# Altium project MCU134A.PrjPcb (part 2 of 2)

## Sheet MCU134A_180pin_Edge_Connector.SchDoc
size 431 x 279 mm; SheetNumber: 11; SheetTotal: 13
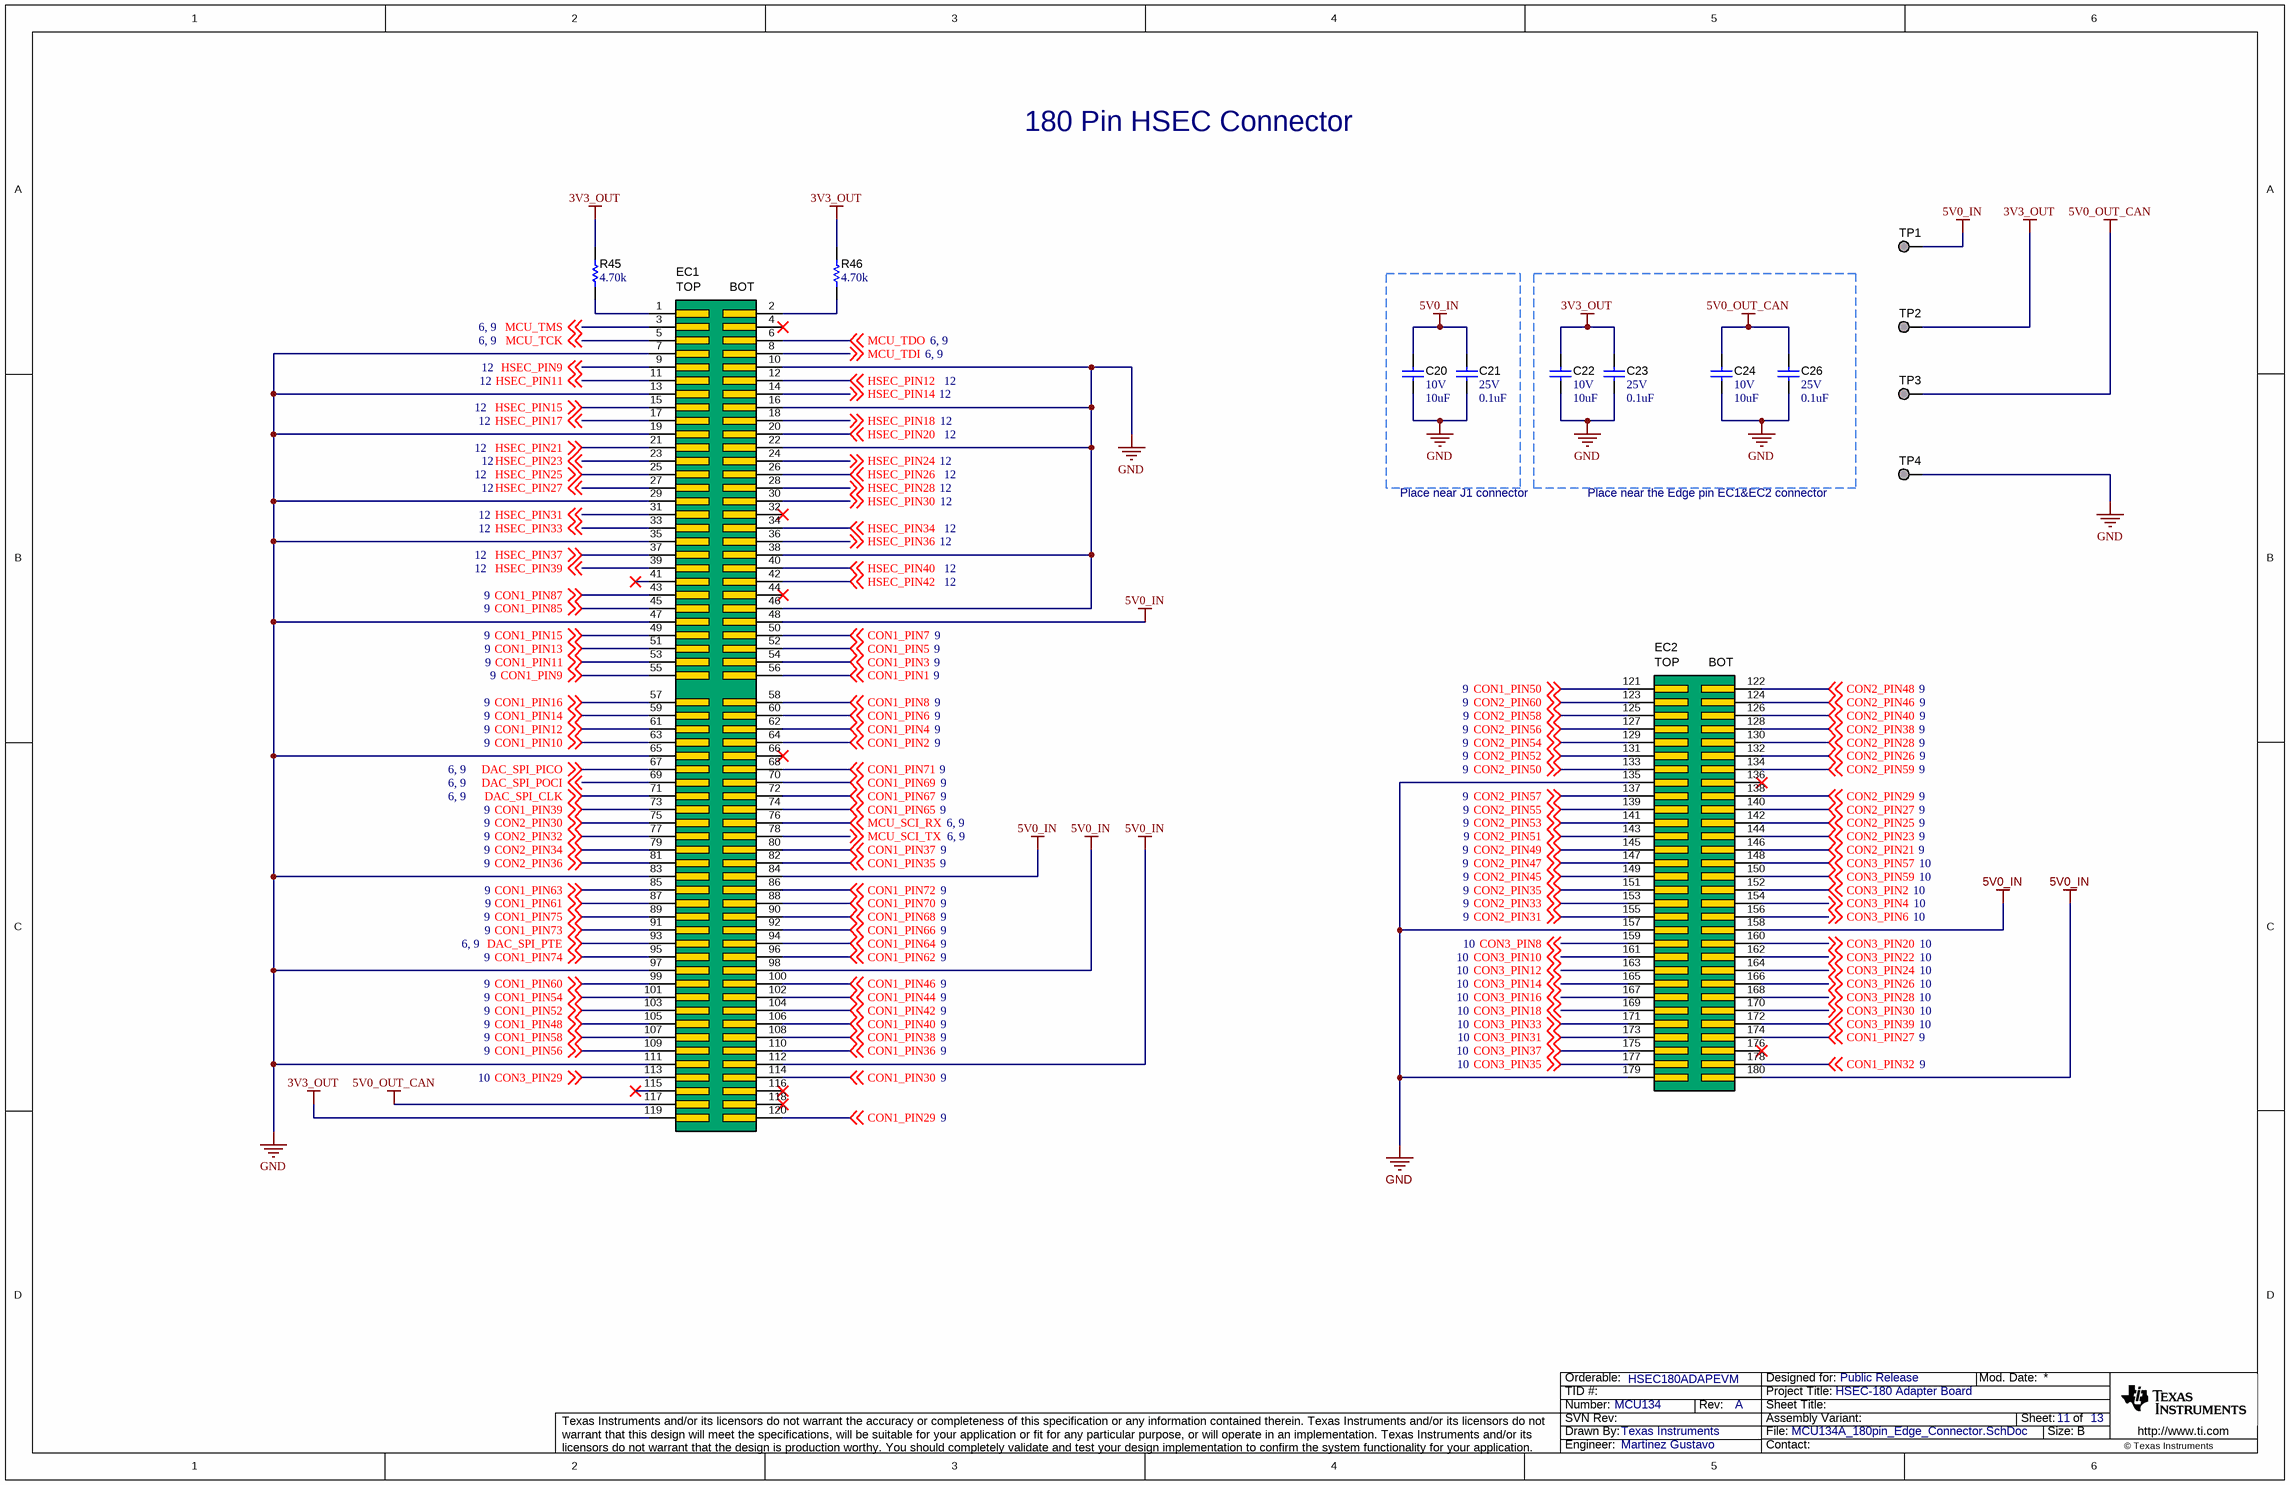
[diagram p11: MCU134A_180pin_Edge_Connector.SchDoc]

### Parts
C20  VDC_V: 10V  ValueDisplayed: 10uF  [0402]  (hidden comment: GRM155R61A106ME11D)
C21  VDC_V: 25V  ValueDisplayed: 0.1uF  [0402]  (hidden comment: GRM155R71E104KE14D)
C22  VDC_V: 10V  ValueDisplayed: 10uF  [0402]  (hidden comment: GRM155R61A106ME11D)
C23  VDC_V: 25V  ValueDisplayed: 0.1uF  [0402]  (hidden comment: GRM155R71E104KE14D)
C24  VDC_V: 10V  ValueDisplayed: 10uF  [0402]  (hidden comment: GRM155R61A106ME11D)
C26  VDC_V: 25V  ValueDisplayed: 0.1uF  [0402]  (hidden comment: GRM155R71E104KE14D)
EC1  controlCARD-120HSEC_Edge  [controlCARD-120HSEC_Edge]  (value not drawn)  (no BOM)
EC2  controlCARD-180HSEC-60pinAddon_Edge  [controlCARD-180HSEC-60pinAddon_Edge]  (value not drawn)  (no BOM)
R45  ValueDisplayed: 4.70k  [0402]  (hidden comment: CRG0402F4K7)
R46  ValueDisplayed: 4.70k  [0402]  (hidden comment: CRG0402F4K7)
TP1  CMP-0078143-4  [TESTPOINT]  (value not drawn)  (no BOM)
TP2  CMP-0078143-4  [TESTPOINT]  (value not drawn)  (no BOM)
TP3  CMP-0078143-4  [TESTPOINT]  (value not drawn)  (no BOM)
TP4  CMP-0078143-4  [TESTPOINT]  (value not drawn)  (no BOM)

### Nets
3V3_OUT: C22.1 C23.1 EC1.119 R45.2 R46.2 TP2.1
5V0_IN: C20.1 C21.1 EC1.48 EC1.84 EC1.98 EC1.112 EC2.158 EC2.180 TP1.1
5V0_OUT_CAN: C24.1 C26.1 EC1.117 TP3.1
GND: C20.2 C21.2 C22.2 C23.2 C24.2 C26.2 EC1.7 EC1.10 EC1.13 EC1.16 EC1.19 EC1.22 EC1.29 EC1.35 EC1.38 EC1.46 EC1.47 EC1.65 EC1.83 EC1.97 EC1.111 EC2.135 EC2.157 EC2.179 TP4.1
CON1_PIN1: EC1.56 ; off-sheet CON1_PIN1
CON1_PIN2: EC1.64 ; off-sheet CON1_PIN2
CON1_PIN3: EC1.54 ; off-sheet CON1_PIN3
CON1_PIN4: EC1.62 ; off-sheet CON1_PIN4
CON1_PIN5: EC1.52 ; off-sheet CON1_PIN5
CON1_PIN6: EC1.60 ; off-sheet CON1_PIN6
CON1_PIN7: EC1.50 ; off-sheet CON1_PIN7
CON1_PIN8: EC1.58 ; off-sheet CON1_PIN8
CON1_PIN9: EC1.55 ; off-sheet CON1_PIN9
CON1_PIN10: EC1.63 ; off-sheet CON1_PIN10
CON1_PIN11: EC1.53 ; off-sheet CON1_PIN11
CON1_PIN12: EC1.61 ; off-sheet CON1_PIN12
CON1_PIN13: EC1.51 ; off-sheet CON1_PIN13
CON1_PIN14: EC1.59 ; off-sheet CON1_PIN14
CON1_PIN15: EC1.49 ; off-sheet CON1_PIN15
CON1_PIN16: EC1.57 ; off-sheet CON1_PIN16
CON1_PIN27: EC2.174 ; off-sheet CON1_PIN27
CON1_PIN29: EC1.120 ; off-sheet CON1_PIN29
CON1_PIN30: EC1.114 ; off-sheet CON1_PIN30
CON1_PIN32: EC2.178 ; off-sheet CON1_PIN32
CON1_PIN35: EC1.82 ; off-sheet CON1_PIN35
CON1_PIN36: EC1.110 ; off-sheet CON1_PIN36
CON1_PIN37: EC1.80 ; off-sheet CON1_PIN37
CON1_PIN38: EC1.108 ; off-sheet CON1_PIN38
CON1_PIN39: EC1.73 ; off-sheet CON1_PIN39
CON1_PIN40: EC1.106 ; off-sheet CON1_PIN40
CON1_PIN42: EC1.104 ; off-sheet CON1_PIN42
CON1_PIN44: EC1.102 ; off-sheet CON1_PIN44
CON1_PIN46: EC1.100 ; off-sheet CON1_PIN46
CON1_PIN48: EC1.105 ; off-sheet CON1_PIN48
CON1_PIN50: EC2.121 ; off-sheet CON1_PIN50
CON1_PIN52: EC1.103 ; off-sheet CON1_PIN52
CON1_PIN54: EC1.101 ; off-sheet CON1_PIN54
CON1_PIN56: EC1.109 ; off-sheet CON1_PIN56
CON1_PIN58: EC1.107 ; off-sheet CON1_PIN58
CON1_PIN60: EC1.99 ; off-sheet CON1_PIN60
CON1_PIN61: EC1.87 ; off-sheet CON1_PIN61
CON1_PIN62: EC1.96 ; off-sheet CON1_PIN62
CON1_PIN63: EC1.85 ; off-sheet CON1_PIN63
CON1_PIN64: EC1.94 ; off-sheet CON1_PIN64
CON1_PIN65: EC1.74 ; off-sheet CON1_PIN65
CON1_PIN66: EC1.92 ; off-sheet CON1_PIN66
CON1_PIN67: EC1.72 ; off-sheet CON1_PIN67
CON1_PIN68: EC1.90 ; off-sheet CON1_PIN68
CON1_PIN69: EC1.70 ; off-sheet CON1_PIN69
CON1_PIN70: EC1.88 ; off-sheet CON1_PIN70
CON1_PIN71: EC1.68 ; off-sheet CON1_PIN71
CON1_PIN72: EC1.86 ; off-sheet CON1_PIN72
CON1_PIN73: EC1.91 ; off-sheet CON1_PIN73
CON1_PIN74: EC1.95 ; off-sheet CON1_PIN74
CON1_PIN75: EC1.89 ; off-sheet CON1_PIN75
CON1_PIN85: EC1.45 ; off-sheet CON1_PIN85
CON1_PIN87: EC1.43 ; off-sheet CON1_PIN87
CON2_PIN21: EC2.146 ; off-sheet CON2_PIN21
CON2_PIN23: EC2.144 ; off-sheet CON2_PIN23
CON2_PIN25: EC2.142 ; off-sheet CON2_PIN25
CON2_PIN26: EC2.132 ; off-sheet CON2_PIN26
CON2_PIN27: EC2.140 ; off-sheet CON2_PIN27
CON2_PIN28: EC2.130 ; off-sheet CON2_PIN28
CON2_PIN29: EC2.138 ; off-sheet CON2_PIN29
CON2_PIN30: EC1.75 ; off-sheet CON2_PIN30
CON2_PIN31: EC2.155 ; off-sheet CON2_PIN31
CON2_PIN32: EC1.77 ; off-sheet CON2_PIN32
CON2_PIN33: EC2.153 ; off-sheet CON2_PIN33
CON2_PIN34: EC1.79 ; off-sheet CON2_PIN34
CON2_PIN35: EC2.151 ; off-sheet CON2_PIN35
CON2_PIN36: EC1.81 ; off-sheet CON2_PIN36
CON2_PIN38: EC2.128 ; off-sheet CON2_PIN38
CON2_PIN40: EC2.126 ; off-sheet CON2_PIN40
CON2_PIN45: EC2.149 ; off-sheet CON2_PIN45
CON2_PIN46: EC2.124 ; off-sheet CON2_PIN46
CON2_PIN47: EC2.147 ; off-sheet CON2_PIN47
CON2_PIN48: EC2.122 ; off-sheet CON2_PIN48
CON2_PIN49: EC2.145 ; off-sheet CON2_PIN49
CON2_PIN50: EC2.133 ; off-sheet CON2_PIN50
CON2_PIN51: EC2.143 ; off-sheet CON2_PIN51
CON2_PIN52: EC2.131 ; off-sheet CON2_PIN52
CON2_PIN53: EC2.141 ; off-sheet CON2_PIN53
CON2_PIN54: EC2.129 ; off-sheet CON2_PIN54
CON2_PIN55: EC2.139 ; off-sheet CON2_PIN55
CON2_PIN56: EC2.127 ; off-sheet CON2_PIN56
CON2_PIN57: EC2.137 ; off-sheet CON2_PIN57
CON2_PIN58: EC2.125 ; off-sheet CON2_PIN58
CON2_PIN59: EC2.134 ; off-sheet CON2_PIN59
CON2_PIN60: EC2.123 ; off-sheet CON2_PIN60
CON3_PIN2: EC2.152 ; off-sheet CON3_PIN2
CON3_PIN4: EC2.154 ; off-sheet CON3_PIN4
CON3_PIN6: EC2.156 ; off-sheet CON3_PIN6
CON3_PIN8: EC2.159 ; off-sheet CON3_PIN8
CON3_PIN10: EC2.161 ; off-sheet CON3_PIN10
CON3_PIN12: EC2.163 ; off-sheet CON3_PIN12
CON3_PIN14: EC2.165 ; off-sheet CON3_PIN14
CON3_PIN16: EC2.167 ; off-sheet CON3_PIN16
CON3_PIN18: EC2.169 ; off-sheet CON3_PIN18
CON3_PIN20: EC2.160 ; off-sheet CON3_PIN20
CON3_PIN22: EC2.162 ; off-sheet CON3_PIN22
CON3_PIN24: EC2.164 ; off-sheet CON3_PIN24
CON3_PIN26: EC2.166 ; off-sheet CON3_PIN26
CON3_PIN28: EC2.168 ; off-sheet CON3_PIN28
CON3_PIN29: EC1.113 ; off-sheet CON3_PIN29
CON3_PIN30: EC2.170 ; off-sheet CON3_PIN30
CON3_PIN31: EC2.173 ; off-sheet CON3_PIN31
CON3_PIN33: EC2.171 ; off-sheet CON3_PIN33
CON3_PIN35: EC2.177 ; off-sheet CON3_PIN35
CON3_PIN37: EC2.175 ; off-sheet CON3_PIN37
CON3_PIN39: EC2.172 ; off-sheet CON3_PIN39
CON3_PIN57: EC2.148 ; off-sheet CON3_PIN57
CON3_PIN59: EC2.150 ; off-sheet CON3_PIN59
DAC_SPI_CLK: EC1.71 ; off-sheet DAC_SPI_CLK
DAC_SPI_PICO: EC1.67 ; off-sheet DAC_SPI_PICO
DAC_SPI_POCI: EC1.69 ; off-sheet DAC_SPI_POCI
DAC_SPI_PTE: EC1.93 ; off-sheet DAC_SPI_PTE
HSEC_PIN9: EC1.9 ; off-sheet HSEC_PIN9
HSEC_PIN11: EC1.11 ; off-sheet HSEC_PIN11
HSEC_PIN12: EC1.12 ; off-sheet HSEC_PIN12
HSEC_PIN14: EC1.14 ; off-sheet HSEC_PIN14
HSEC_PIN15: EC1.15 ; off-sheet HSEC_PIN15
HSEC_PIN17: EC1.17 ; off-sheet HSEC_PIN17
HSEC_PIN18: EC1.18 ; off-sheet HSEC_PIN18
HSEC_PIN20: EC1.20 ; off-sheet HSEC_PIN20
HSEC_PIN21: EC1.21 ; off-sheet HSEC_PIN21
HSEC_PIN23: EC1.23 ; off-sheet HSEC_PIN23
HSEC_PIN24: EC1.24 ; off-sheet HSEC_PIN24
HSEC_PIN25: EC1.25 ; off-sheet HSEC_PIN25
HSEC_PIN26: EC1.26 ; off-sheet HSEC_PIN26
HSEC_PIN27: EC1.27 ; off-sheet HSEC_PIN27
HSEC_PIN28: EC1.28 ; off-sheet HSEC_PIN28
HSEC_PIN30: EC1.30 ; off-sheet HSEC_PIN30
HSEC_PIN31: EC1.31 ; off-sheet HSEC_PIN31
HSEC_PIN33: EC1.33 ; off-sheet HSEC_PIN33
HSEC_PIN34: EC1.34 ; off-sheet HSEC_PIN34
HSEC_PIN36: EC1.36 ; off-sheet HSEC_PIN36
HSEC_PIN37: EC1.37 ; off-sheet HSEC_PIN37
HSEC_PIN39: EC1.39 ; off-sheet HSEC_PIN39
HSEC_PIN40: EC1.40 ; off-sheet HSEC_PIN40
HSEC_PIN42: EC1.42 ; off-sheet HSEC_PIN42
MCU_SCI_RX: EC1.76 ; off-sheet MCU_SCI_RX
MCU_SCI_TX: EC1.78 ; off-sheet MCU_SCI_TX
MCU_TCK: EC1.5 ; off-sheet MCU_TCK
MCU_TDI: EC1.8 ; off-sheet MCU_TDI
MCU_TDO: EC1.6 ; off-sheet MCU_TDO
MCU_TMS: EC1.3 ; off-sheet MCU_TMS
NetEC1_1: EC1.1 R45.1
NetEC1_2: EC1.2 R46.1

Not connected (* = marked no-connect by the designer): EC1 4* 32* 41* 44* 66* 115* 116* 118*; EC2 136* 176*

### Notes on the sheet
- 180 Pin HSEC Connector
- Place near J1 connector
- Place near the Edge pin EC1&EC2 connector

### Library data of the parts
C20 C22 C24 = CMP-0006564-3: CAP, CERM, 10 uF, 10 V, +/- 20%, X5R, 0402; Manufacturer: MuRata; Cap_F: 10µF; U/M: EA; Value1: Unknown; AEC Category: Q200; SizeX_mm: 1; SizeY_mm: 0.5; SizeZ_mm: 0.6; Value: 10uF; TaMin_C: -55°C; Polarized: N; SizeAreaWB_mm2: 3; TaMax_C: 85°C
C21 C23 C26 = CMP-0006659-2: CAP, CERM, 0.1 uF, 25 V, +/- 10%, X7R, 0402; Manufacturer: MuRata; TaMin_C: -55°C; Polarized: N; SizeAreaWB_mm2: 3; Value1: Unknown; U/M: EA; Value: 0.1uF; TaMax_C: 125°C; SizeZ_mm: 0.6; SizeX_mm: 1; SizeY_mm: 0.5; Cap_F: 100nF; AEC Category: Q200
EC1 = CMP-0003813-3: C2000 controlCARD-120HSEC Edge Connector for Samtec HSEC8-160-01-L-DV-A-BL; Manufacturer: Any; Note: The pin numbering does not match Samtec datasheet
EC2 = CMP-0081961-1: C2000 controlCARD-180HSEC (60-pin addon) Edge connector for Samtec HSEC8-130-01-L-DV-A; Manufacturer: Any; Note: The pin numbering does not match Samtec datasheet
R45 R46 = CMP-0026631-1: RES, 4.70 k, 1%, 0.063 W, 0402; Manufacturer: TE Connectivity; Power_W: 63mW; TempCo: 100 ppm/C; Value_Code: 4k70; U/M: EA; Value: 4.70k; Res_ohm: 4.7k; SizeX_mm: 1; SizeY_mm: 0.5; SizeZ_mm: 0.6; Value2: 0.063W; AEC Qualified: N; AEC Category: Q200
TP1-TP4 = CMP-0078143-4: TEST POINT.  No entry in BOM.

## Sheet MCU134A_ADC.SchDoc
size 431 x 279 mm; SheetNumber: 12; SheetTotal: 13
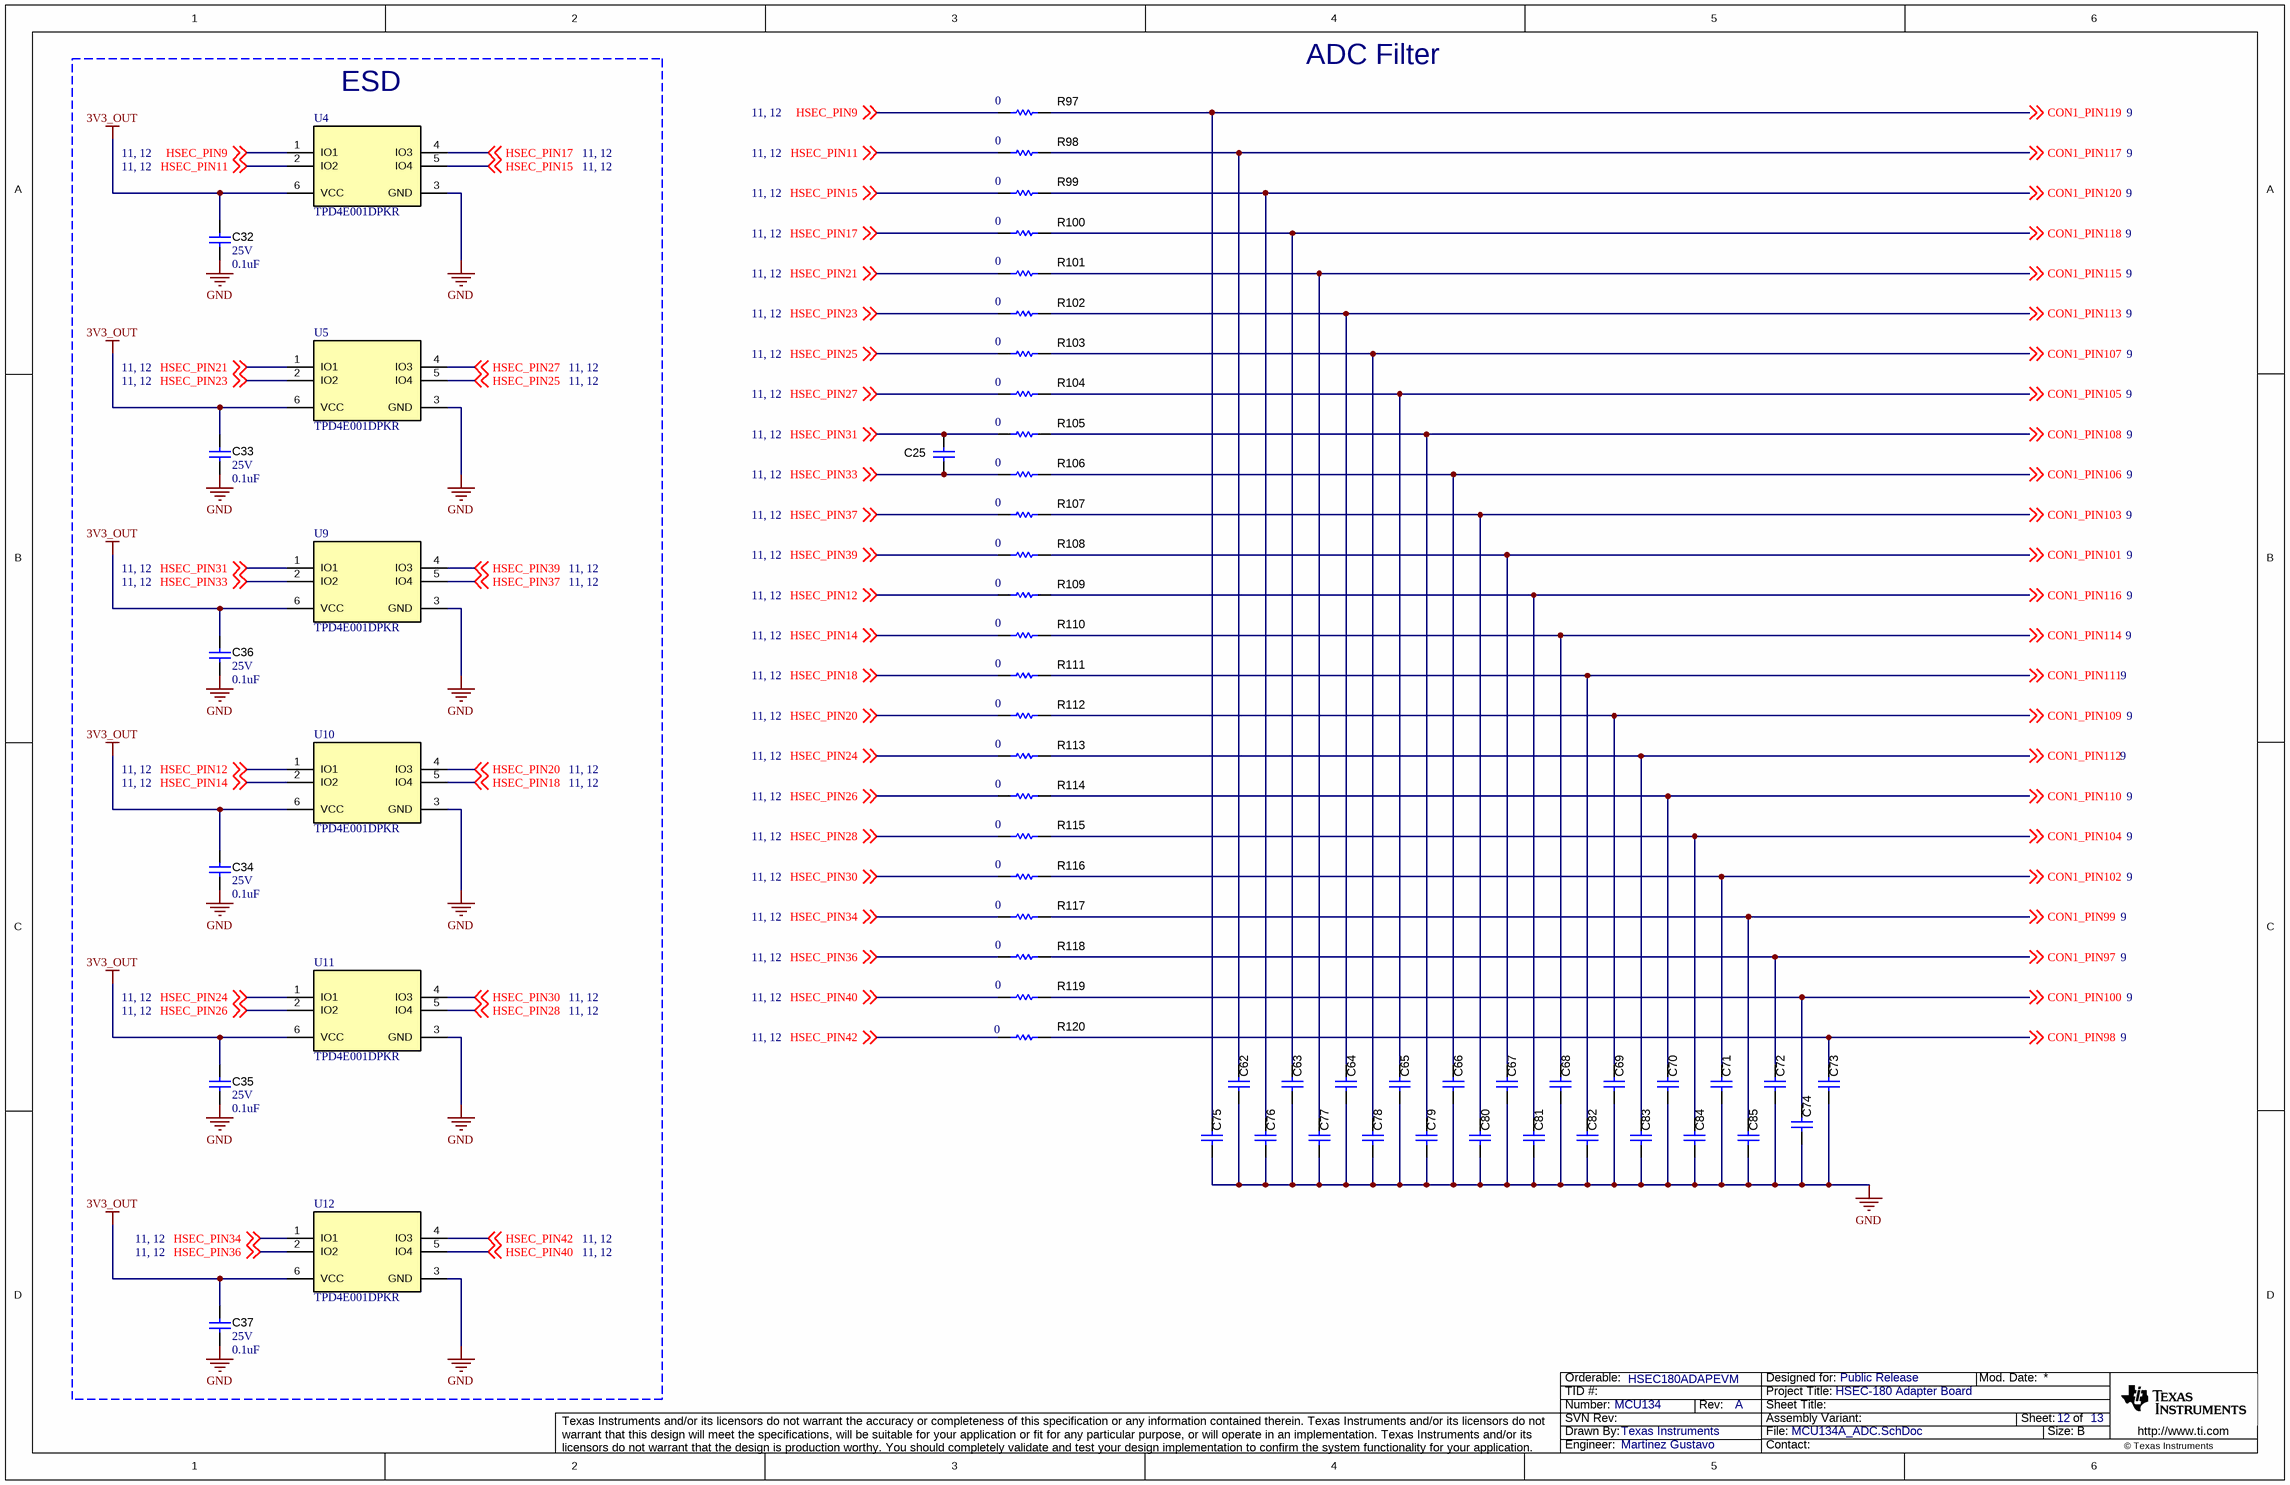
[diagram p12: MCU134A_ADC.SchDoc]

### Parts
C25  GRM155R71E104KE14D  [0402]  (value not drawn)
C32  VDC_V: 25V  ValueDisplayed: 0.1uF  [0402]  (hidden comment: GRM155R71E104KE14D)
C33  VDC_V: 25V  ValueDisplayed: 0.1uF  [0402]  (hidden comment: GRM155R71E104KE14D)
C34  VDC_V: 25V  ValueDisplayed: 0.1uF  [0402]  (hidden comment: GRM155R71E104KE14D)
C35  VDC_V: 25V  ValueDisplayed: 0.1uF  [0402]  (hidden comment: GRM155R71E104KE14D)
C36  VDC_V: 25V  ValueDisplayed: 0.1uF  [0402]  (hidden comment: GRM155R71E104KE14D)
C37  VDC_V: 25V  ValueDisplayed: 0.1uF  [0402]  (hidden comment: GRM155R71E104KE14D)
C62  885012006060  [0603]  (value not drawn)
C63  885012006060  [0603]  (value not drawn)
C64  885012006060  [0603]  (value not drawn)
C65  885012006060  [0603]  (value not drawn)
C66  885012006060  [0603]  (value not drawn)
C67  885012006060  [0603]  (value not drawn)
C68  885012006060  [0603]  (value not drawn)
C69  885012006060  [0603]  (value not drawn)
C70  885012006060  [0603]  (value not drawn)
C71  885012006060  [0603]  (value not drawn)
C72  885012006060  [0603]  (value not drawn)
C73  885012006060  [0603]  (value not drawn)
C74  885012006060  [0603]  (value not drawn)
C75  885012006060  [0603]  (value not drawn)
C76  885012006060  [0603]  (value not drawn)
C77  885012006060  [0603]  (value not drawn)
C78  885012006060  [0603]  (value not drawn)
C79  885012006060  [0603]  (value not drawn)
C80  885012006060  [0603]  (value not drawn)
C81  885012006060  [0603]  (value not drawn)
C82  885012006060  [0603]  (value not drawn)
C83  885012006060  [0603]  (value not drawn)
C84  885012006060  [0603]  (value not drawn)
C85  885012006060  [0603]  (value not drawn)
R97  value 0  [0402]  (hidden comment: CRCW04020000Z0ED)
R98  value 0  [0402]  (hidden comment: CRCW04020000Z0ED)
R99  value 0  [0402]  (hidden comment: CRCW04020000Z0ED)
R100  value 0  [0402]  (hidden comment: CRCW04020000Z0ED)
R101  value 0  [0402]  (hidden comment: CRCW04020000Z0ED)
R102  value 0  [0402]  (hidden comment: CRCW04020000Z0ED)
R103  value 0  [0402]  (hidden comment: CRCW04020000Z0ED)
R104  value 0  [0402]  (hidden comment: CRCW04020000Z0ED)
R105  value 0  [0402]  (hidden comment: CRCW04020000Z0ED)
R106  value 0  [0402]  (hidden comment: CRCW04020000Z0ED)
R107  value 0  [0402]  (hidden comment: CRCW04020000Z0ED)
R108  value 0  [0402]  (hidden comment: CRCW04020000Z0ED)
R109  value 0  [0402]  (hidden comment: CRCW04020000Z0ED)
R110  value 0  [0402]  (hidden comment: CRCW04020000Z0ED)
R111  value 0  [0402]  (hidden comment: CRCW04020000Z0ED)
R112  value 0  [0402]  (hidden comment: CRCW04020000Z0ED)
R113  value 0  [0402]  (hidden comment: CRCW04020000Z0ED)
R114  value 0  [0402]  (hidden comment: CRCW04020000Z0ED)
R115  value 0  [0402]  (hidden comment: CRCW04020000Z0ED)
R116  value 0  [0402]  (hidden comment: CRCW04020000Z0ED)
R117  value 0  [0402]  (hidden comment: CRCW04020000Z0ED)
R118  value 0  [0402]  (hidden comment: CRCW04020000Z0ED)
R119  value 0  [0402]  (hidden comment: CRCW04020000Z0ED)
R120  value 0  [0402]  (hidden comment: CRCW04020000Z0ED)
U4  TPD4E001DPKR  [DPK0006A]
U5  TPD4E001DPKR  [DPK0006A]
U9  TPD4E001DPKR  [DPK0006A]
U10  TPD4E001DPKR  [DPK0006A]
U11  TPD4E001DPKR  [DPK0006A]
U12  TPD4E001DPKR  [DPK0006A]

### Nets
3V3_OUT: C32.1 C33.1 C34.1 C35.1 C36.1 C37.1 U4.6(VCC) U5.6(VCC) U9.6(VCC) U10.6(VCC) U11.6(VCC) U12.6(VCC)
GND: C32.2 C33.2 C34.2 C35.2 C36.2 C37.2 C62.2 C63.2 C64.2 C65.2 C66.2 C67.2 C68.2 C69.2 C70.2 C71.2 C72.2 C73.2 C74.2 C75.2 C76.2 C77.2 C78.2 C79.2 C80.2 C81.2 C82.2 C83.2 C84.2 C85.2 U4.3(GND) U5.3(GND) U9.3(GND) U10.3(GND) U11.3(GND) U12.3(GND)
CON1_PIN97: C72.1 R118.2 ; off-sheet CON1_PIN97
CON1_PIN98: C73.1 R120.2 ; off-sheet CON1_PIN98
CON1_PIN99: C85.1 R117.2 ; off-sheet CON1_PIN99
CON1_PIN100: C74.1 R119.2 ; off-sheet CON1_PIN100
CON1_PIN101: C67.1 R108.2 ; off-sheet CON1_PIN101
CON1_PIN102: C71.1 R116.2 ; off-sheet CON1_PIN102
CON1_PIN103: C80.1 R107.2 ; off-sheet CON1_PIN103
CON1_PIN104: C84.1 R115.2 ; off-sheet CON1_PIN104
CON1_PIN105: C65.1 R104.2 ; off-sheet CON1_PIN105
CON1_PIN106: C66.1 R106.2 ; off-sheet CON1_PIN106
CON1_PIN107: C78.1 R103.2 ; off-sheet CON1_PIN107
CON1_PIN108: C79.1 R105.2 ; off-sheet CON1_PIN108
CON1_PIN109: C69.1 R112.2 ; off-sheet CON1_PIN109
CON1_PIN110: C70.1 R114.2 ; off-sheet CON1_PIN110
CON1_PIN111: C82.1 R111.2 ; off-sheet CON1_PIN111
CON1_PIN112: C83.1 R113.2 ; off-sheet CON1_PIN112
CON1_PIN113: C64.1 R102.2 ; off-sheet CON1_PIN113
CON1_PIN114: C68.1 R110.2 ; off-sheet CON1_PIN114
CON1_PIN115: C77.1 R101.2 ; off-sheet CON1_PIN115
CON1_PIN116: C81.1 R109.2 ; off-sheet CON1_PIN116
CON1_PIN117: C62.1 R98.2 ; off-sheet CON1_PIN117
CON1_PIN118: C63.1 R100.2 ; off-sheet CON1_PIN118
CON1_PIN119: C75.1 R97.2 ; off-sheet CON1_PIN119
CON1_PIN120: C76.1 R99.2 ; off-sheet CON1_PIN120
HSEC_PIN9: R97.1 U4.1(IO1) ; off-sheet HSEC_PIN9
HSEC_PIN11: R98.1 U4.2(IO2) ; off-sheet HSEC_PIN11
HSEC_PIN12: R109.1 U10.1(IO1) ; off-sheet HSEC_PIN12
HSEC_PIN14: R110.1 U10.2(IO2) ; off-sheet HSEC_PIN14
HSEC_PIN15: R99.1 U4.5(IO4) ; off-sheet HSEC_PIN15
HSEC_PIN17: R100.1 U4.4(IO3) ; off-sheet HSEC_PIN17
HSEC_PIN18: R111.1 U10.5(IO4) ; off-sheet HSEC_PIN18
HSEC_PIN20: R112.1 U10.4(IO3) ; off-sheet HSEC_PIN20
HSEC_PIN21: R101.1 U5.1(IO1) ; off-sheet HSEC_PIN21
HSEC_PIN23: R102.1 U5.2(IO2) ; off-sheet HSEC_PIN23
HSEC_PIN24: R113.1 U11.1(IO1) ; off-sheet HSEC_PIN24
HSEC_PIN25: R103.1 U5.5(IO4) ; off-sheet HSEC_PIN25
HSEC_PIN26: R114.1 U11.2(IO2) ; off-sheet HSEC_PIN26
HSEC_PIN27: R104.1 U5.4(IO3) ; off-sheet HSEC_PIN27
HSEC_PIN28: R115.1 U11.5(IO4) ; off-sheet HSEC_PIN28
HSEC_PIN30: R116.1 U11.4(IO3) ; off-sheet HSEC_PIN30
HSEC_PIN31: C25.1 R105.1 U9.1(IO1) ; off-sheet HSEC_PIN31
HSEC_PIN33: C25.2 R106.1 U9.2(IO2) ; off-sheet HSEC_PIN33
HSEC_PIN34: R117.1 U12.1(IO1) ; off-sheet HSEC_PIN34
HSEC_PIN36: R118.1 U12.2(IO2) ; off-sheet HSEC_PIN36
HSEC_PIN37: R107.1 U9.5(IO4) ; off-sheet HSEC_PIN37
HSEC_PIN39: R108.1 U9.4(IO3) ; off-sheet HSEC_PIN39
HSEC_PIN40: R119.1 U12.5(IO4) ; off-sheet HSEC_PIN40
HSEC_PIN42: R120.1 U12.4(IO3) ; off-sheet HSEC_PIN42

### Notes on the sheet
- ESD
- ADC Filter

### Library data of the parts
C25 = CMP-0006659-2: CAP, CERM, 0.1 uF, 25 V, +/- 10%, X7R, 0402; Manufacturer: MuRata; TaMin_C: -55°C; Polarized: N; SizeAreaWB_mm2: 3; Value1: Unknown; U/M: EA; Value: 0.1uF; TaMax_C: 125°C; SizeZ_mm: 0.6; SizeX_mm: 1; SizeY_mm: 0.5; Value2: 25V; Cap_F: 100nF; AEC Category: Q200
C32-C37 = CMP-0006659-2: as C21 on sheet MCU134A_180pin_Edge_Connector
C62-C85 = CMP-0006823-4: CAP, CERM, 330 pF, 50 V, +/- 5%, C0G/NP0, 0603; Manufacturer: Wurth Elektronik; TaMin_C: -55°C; Polarized: N; SizeAreaWB_mm2: 4.68; Value1: Unknown; U/M: EA; Value: 330pF; TaMax_C: 125°C; SizeZ_mm: 1; SizeX_mm: 1.6; SizeY_mm: 0.8; Value2: 50V; SizeArea_mm2: 1.28; AEC Category: Q200
R97-R120 = CMP-0026822-3: RES, 0, 5%, 0.063 W, AEC-Q200 Grade 0, 0402; Manufacturer: Vishay-Dale; Power_W: 63mW; SizeZ_mm: 0.6; AEC Qualified: Y; AEC Category: Q200; EIA_Code: E24; SizeArea_mm2: 0.5; SizeX_mm: 1; TempCo: 200 ppm/C; Value2: 0.063W; Value_Code: 0000; VDC_V: 50V
U4 U5 U9-U12 = CMP-0043110-1: Low-Capacitance + / - 15-kV ESD Protection Array for High-Speed Data Interfaces, 4 Channels, -40 to +85 degC, 6-pin USON (DPK), Green (RoHS & no Sb/Br); Manufacturer: Texas Instruments; IO Capacitance(Typ)(pF): 1.5; IEC 61000-4-2 Contact(+/- kV): 8; SubFamily: ESD Solution; Breakdown Voltage(Min)(V): 11; 1394 / Firewire: TRUE; IEC 61000-4-2 Air-Gap(+/- kV): 15

## Sheet MCU134A_EVM_Hardware.SchDoc
size 431 x 279 mm; Date: Not shown in title block; ApprovedBy: Not shown in title block; CheckedBy: Not shown in title block; Author: Not shown in title block; CompanyName: Not shown in title block; Engineer: Not shown in title block; Organization: Not shown in title block; Address1: Not shown in title block; Address2: Not shown in title block; Address3: Not shown in title block; Address4: Not shown in title block; DocumentNumber: 9; Revision: Use project parameter SCH_Rev; SheetNumber: 13; SheetTotal: 13; PageSetup: Record=PageOptions¦CenterHorizontal=True¦CenterVertical=True¦PrintScale=1.00¦XCorrection=1.00¦YCorrection=1.00¦PrintKind=0¦BorderSize=5000000¦LeftOffset=0¦BottomOffset=0¦Orientation=2¦PaperLength=1000¦PaperWidth=1000¦Scale=100¦PaperSource=15¦PrintQuality=600¦MediaType=1¦DitherType=10¦PaperKind=Letter¦PrintScaleMode=1
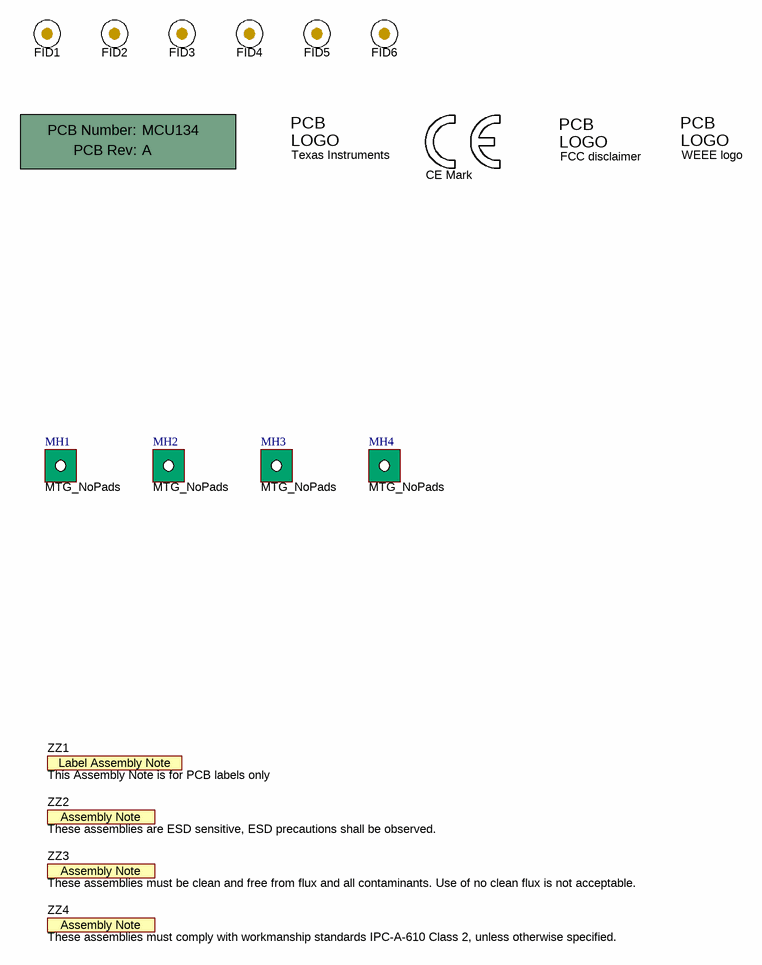
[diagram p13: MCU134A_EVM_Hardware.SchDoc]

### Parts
!PCB1  Printed Circuit Board  (value not drawn)  (mechanical)
FID1  Fiducial  [Fiducial10-20]  (value not drawn)
FID2  Fiducial  [Fiducial10-20]  (value not drawn)
FID3  Fiducial  [Fiducial10-20]  (value not drawn)
FID4  Fiducial  [Fiducial10-20]  (value not drawn)
FID5  Fiducial  [Fiducial10-20]  (value not drawn)
FID6  Fiducial  [Fiducial10-20]  (value not drawn)
Logo1  CE Mark  [CE_Mark_5mm]  (no BOM)
Logo2  Texas Instruments  [TI_Stacked_Overlay_Small]  (no BOM)
Logo3  FCC disclaimer  [FCC_disclaimer]  (no BOM)
Logo4  WEEE logo  [WEEE_Minimum]  (no BOM)
MH1  MTG_NoPads  [MTG_159mil]  (no BOM)
MH2  MTG_NoPads  [MTG_159mil]  (no BOM)
MH3  MTG_NoPads  [MTG_159mil]  (no BOM)
MH4  MTG_NoPads  [MTG_159mil]  (no BOM)
ZZ1  This Assembly Note is for PCB labels only  [AssemblyNoteLabel]  (no BOM)
ZZ2  These assemblies are ESD sensitive, ESD precautions shall be observed.  [AssemblyNote]  (no BOM)
ZZ3  These assemblies must be clean and free from flux and all contaminants. Use of no clean flux is not acceptable.  [AssemblyNote]  (no BOM)
ZZ4  These assemblies must comply with workmanship standards IPC-A-610 Class 2, unless otherwise specified.  [AssemblyNote]  (no BOM)

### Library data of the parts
!PCB1 = CMP-0003618-2: Manufacturer: Any; PartNumber: MCU134
FID1-FID6 = CMP-0077181-1: Fiducial mark.  There is nothing to buy or mount.
Logo1 = CMP-0074844-1: SymbolCreator: a0412235
Logo2 = CMP-0074838-1: Texas Instrument Corporate Signature; SymbolCreator: a0412235; Lib Reference: TI_Logo; Library Reference: Logo
Logo3 = CMP-0074847-1: FCC_disclaimer
Logo4 = CMP-0074769-3: Manufacturer: Texas Instruments; AEC Category: Q200; CompType: IC
MH1-MH4 = CMP-0078424-2: PCB Mounting Hole, No Pad; Manufacturer: Any; Key: Mounting Hole (non-standard) No Pad
ZZ1 = CMP-0003616-3
ZZ2 = CMP-0077236-1
ZZ3 = CMP-0077237-1
ZZ4 = CMP-0077238-1

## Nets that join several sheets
3V3_ETH: MCU134A_EtherCAT_PHY_0 (16 pins), MCU134A_EtherCAT_PHY_1 (8 pins)
3V3_OUT: MCU134A_FSI_Header (J7.1 J8.10), MCU134A_EtherCAT_PHY_0 (R35.1), MCU134A_High_Density_Conn1_2 (J1.28), MCU134A_180pin_Edge_Connector (6 pins), MCU134A_ADC (12 pins)
5V0_IN: MCU134A_High_Density_Conn1_2 (J1.18 J1.20 R36.2), MCU134A_High_Density_Conn3_4 (J3.27), MCU134A_180pin_Edge_Connector (9 pins)
5V0_OUT_CAN: MCU134A_High_Density_Conn1_2 (J1.34), MCU134A_180pin_Edge_Connector (C24.1 C26.1 EC1.117 TP3.1)
GND: MCU134A_FSI_Header (J7.2 J7.7 J8.4 J8.8), MCU134A_EtherCAT_PHY_0 (41 pins), MCU134A_EtherCAT_PHY_1 (30 pins), MCU134A_High_Density_Conn1_2 (19 pins), MCU134A_High_Density_Conn3_4 (16 pins), MCU134A_180pin_Edge_Connector (25 pins), MCU134A_ADC (36 pins)
SHLD_GND: MCU134A_EtherCAT_PHY_0 (5 pins), MCU134A_EtherCAT_PHY_1 (5 pins)
CON1_PIN1: MCU134A_High_Density_Conn1_2 (J1.1), MCU134A_180pin_Edge_Connector (EC1.56)
CON1_PIN2: MCU134A_High_Density_Conn1_2 (J1.2), MCU134A_180pin_Edge_Connector (EC1.64)
CON1_PIN3: MCU134A_High_Density_Conn1_2 (J1.3), MCU134A_180pin_Edge_Connector (EC1.54)
CON1_PIN4: MCU134A_High_Density_Conn1_2 (J1.4), MCU134A_180pin_Edge_Connector (EC1.62)
CON1_PIN5: MCU134A_High_Density_Conn1_2 (J1.5), MCU134A_180pin_Edge_Connector (EC1.52)
CON1_PIN6: MCU134A_High_Density_Conn1_2 (J1.6), MCU134A_180pin_Edge_Connector (EC1.60)
CON1_PIN7: MCU134A_High_Density_Conn1_2 (J1.7), MCU134A_180pin_Edge_Connector (EC1.50)
CON1_PIN8: MCU134A_High_Density_Conn1_2 (J1.8), MCU134A_180pin_Edge_Connector (EC1.58)
CON1_PIN9: MCU134A_High_Density_Conn1_2 (J1.9), MCU134A_180pin_Edge_Connector (EC1.55)
CON1_PIN10: MCU134A_High_Density_Conn1_2 (J1.10), MCU134A_180pin_Edge_Connector (EC1.63)
CON1_PIN11: MCU134A_High_Density_Conn1_2 (J1.11), MCU134A_180pin_Edge_Connector (EC1.53)
CON1_PIN12: MCU134A_High_Density_Conn1_2 (J1.12), MCU134A_180pin_Edge_Connector (EC1.61)
CON1_PIN13: MCU134A_High_Density_Conn1_2 (J1.13), MCU134A_180pin_Edge_Connector (EC1.51)
CON1_PIN14: MCU134A_High_Density_Conn1_2 (J1.14), MCU134A_180pin_Edge_Connector (EC1.59)
CON1_PIN15: MCU134A_High_Density_Conn1_2 (J1.15), MCU134A_180pin_Edge_Connector (EC1.49)
CON1_PIN16: MCU134A_High_Density_Conn1_2 (J1.16), MCU134A_180pin_Edge_Connector (EC1.57)
CON1_PIN27: MCU134A_High_Density_Conn1_2 (J1.27), MCU134A_180pin_Edge_Connector (EC2.174)
CON1_PIN29: MCU134A_High_Density_Conn1_2 (J1.29), MCU134A_180pin_Edge_Connector (EC1.120)
CON1_PIN30: MCU134A_High_Density_Conn1_2 (J1.30), MCU134A_180pin_Edge_Connector (EC1.114)
CON1_PIN32: MCU134A_High_Density_Conn1_2 (J1.32), MCU134A_180pin_Edge_Connector (EC2.178)
CON1_PIN35: MCU134A_High_Density_Conn1_2 (J1.35), MCU134A_180pin_Edge_Connector (EC1.82)
CON1_PIN36: MCU134A_High_Density_Conn1_2 (J1.36), MCU134A_180pin_Edge_Connector (EC1.110)
CON1_PIN37: MCU134A_High_Density_Conn1_2 (J1.37), MCU134A_180pin_Edge_Connector (EC1.80)
CON1_PIN38: MCU134A_High_Density_Conn1_2 (J1.38), MCU134A_180pin_Edge_Connector (EC1.108)
CON1_PIN39: MCU134A_High_Density_Conn1_2 (J1.39), MCU134A_180pin_Edge_Connector (EC1.73)
CON1_PIN40: MCU134A_High_Density_Conn1_2 (J1.40), MCU134A_180pin_Edge_Connector (EC1.106)
CON1_PIN42: MCU134A_High_Density_Conn1_2 (J1.42), MCU134A_180pin_Edge_Connector (EC1.104)
CON1_PIN44: MCU134A_High_Density_Conn1_2 (J1.44), MCU134A_180pin_Edge_Connector (EC1.102)
CON1_PIN46: MCU134A_High_Density_Conn1_2 (J1.46), MCU134A_180pin_Edge_Connector (EC1.100)
CON1_PIN48: MCU134A_High_Density_Conn1_2 (J1.48), MCU134A_180pin_Edge_Connector (EC1.105)
CON1_PIN50: MCU134A_High_Density_Conn1_2 (J1.50), MCU134A_180pin_Edge_Connector (EC2.121)
CON1_PIN52: MCU134A_High_Density_Conn1_2 (J1.52), MCU134A_180pin_Edge_Connector (EC1.103)
CON1_PIN54: MCU134A_High_Density_Conn1_2 (J1.54), MCU134A_180pin_Edge_Connector (EC1.101)
CON1_PIN56: MCU134A_High_Density_Conn1_2 (J1.56), MCU134A_180pin_Edge_Connector (EC1.109)
CON1_PIN58: MCU134A_High_Density_Conn1_2 (J1.58), MCU134A_180pin_Edge_Connector (EC1.107)
CON1_PIN60: MCU134A_High_Density_Conn1_2 (J1.60), MCU134A_180pin_Edge_Connector (EC1.99)
CON1_PIN61: MCU134A_High_Density_Conn1_2 (J1.61), MCU134A_180pin_Edge_Connector (EC1.87)
CON1_PIN62: MCU134A_High_Density_Conn1_2 (J1.62), MCU134A_180pin_Edge_Connector (EC1.96)
CON1_PIN63: MCU134A_High_Density_Conn1_2 (J1.63), MCU134A_180pin_Edge_Connector (EC1.85)
CON1_PIN64: MCU134A_High_Density_Conn1_2 (J1.64), MCU134A_180pin_Edge_Connector (EC1.94)
CON1_PIN65: MCU134A_High_Density_Conn1_2 (J1.65), MCU134A_180pin_Edge_Connector (EC1.74)
CON1_PIN66: MCU134A_High_Density_Conn1_2 (J1.66), MCU134A_180pin_Edge_Connector (EC1.92)
CON1_PIN67: MCU134A_High_Density_Conn1_2 (J1.67), MCU134A_180pin_Edge_Connector (EC1.72)
CON1_PIN68: MCU134A_High_Density_Conn1_2 (J1.68), MCU134A_180pin_Edge_Connector (EC1.90)
CON1_PIN69: MCU134A_High_Density_Conn1_2 (J1.69), MCU134A_180pin_Edge_Connector (EC1.70)
CON1_PIN70: MCU134A_High_Density_Conn1_2 (J1.70), MCU134A_180pin_Edge_Connector (EC1.88)
CON1_PIN71: MCU134A_High_Density_Conn1_2 (J1.71), MCU134A_180pin_Edge_Connector (EC1.68)
CON1_PIN72: MCU134A_High_Density_Conn1_2 (J1.72), MCU134A_180pin_Edge_Connector (EC1.86)
CON1_PIN73: MCU134A_High_Density_Conn1_2 (J1.73), MCU134A_180pin_Edge_Connector (EC1.91)
CON1_PIN74: MCU134A_High_Density_Conn1_2 (J1.74), MCU134A_180pin_Edge_Connector (EC1.95)
CON1_PIN75: MCU134A_High_Density_Conn1_2 (J1.75), MCU134A_180pin_Edge_Connector (EC1.89)
CON1_PIN85: MCU134A_High_Density_Conn1_2 (J1.85), MCU134A_180pin_Edge_Connector (EC1.45)
CON1_PIN87: MCU134A_High_Density_Conn1_2 (J1.87), MCU134A_180pin_Edge_Connector (EC1.43)
CON1_PIN97: MCU134A_High_Density_Conn1_2 (J1.97), MCU134A_ADC (C72.1 R118.2)
CON1_PIN98: MCU134A_High_Density_Conn1_2 (J1.98), MCU134A_ADC (C73.1 R120.2)
CON1_PIN99: MCU134A_High_Density_Conn1_2 (J1.99), MCU134A_ADC (C85.1 R117.2)
CON1_PIN100: MCU134A_High_Density_Conn1_2 (J1.100), MCU134A_ADC (C74.1 R119.2)
CON1_PIN101: MCU134A_High_Density_Conn1_2 (J1.101), MCU134A_ADC (C67.1 R108.2)
CON1_PIN102: MCU134A_High_Density_Conn1_2 (J1.102), MCU134A_ADC (C71.1 R116.2)
CON1_PIN103: MCU134A_High_Density_Conn1_2 (J1.103), MCU134A_ADC (C80.1 R107.2)
CON1_PIN104: MCU134A_High_Density_Conn1_2 (J1.104), MCU134A_ADC (C84.1 R115.2)
CON1_PIN105: MCU134A_High_Density_Conn1_2 (J1.105), MCU134A_ADC (C65.1 R104.2)
CON1_PIN106: MCU134A_High_Density_Conn1_2 (J1.106), MCU134A_ADC (C66.1 R106.2)
CON1_PIN107: MCU134A_High_Density_Conn1_2 (J1.107), MCU134A_ADC (C78.1 R103.2)
CON1_PIN108: MCU134A_High_Density_Conn1_2 (J1.108), MCU134A_ADC (C79.1 R105.2)
CON1_PIN109: MCU134A_High_Density_Conn1_2 (J1.109), MCU134A_ADC (C69.1 R112.2)
CON1_PIN110: MCU134A_High_Density_Conn1_2 (J1.110), MCU134A_ADC (C70.1 R114.2)
CON1_PIN111: MCU134A_High_Density_Conn1_2 (J1.111), MCU134A_ADC (C82.1 R111.2)
CON1_PIN112: MCU134A_High_Density_Conn1_2 (J1.112), MCU134A_ADC (C83.1 R113.2)
CON1_PIN113: MCU134A_High_Density_Conn1_2 (J1.113), MCU134A_ADC (C64.1 R102.2)
CON1_PIN114: MCU134A_High_Density_Conn1_2 (J1.114), MCU134A_ADC (C68.1 R110.2)
CON1_PIN115: MCU134A_High_Density_Conn1_2 (J1.115), MCU134A_ADC (C77.1 R101.2)
CON1_PIN116: MCU134A_High_Density_Conn1_2 (J1.116), MCU134A_ADC (C81.1 R109.2)
CON1_PIN117: MCU134A_High_Density_Conn1_2 (J1.117), MCU134A_ADC (C62.1 R98.2)
CON1_PIN118: MCU134A_High_Density_Conn1_2 (J1.118), MCU134A_ADC (C63.1 R100.2)
CON1_PIN119: MCU134A_High_Density_Conn1_2 (J1.119), MCU134A_ADC (C75.1 R97.2)
CON1_PIN120: MCU134A_High_Density_Conn1_2 (J1.120), MCU134A_ADC (C76.1 R99.2)
CON2_PIN21: MCU134A_High_Density_Conn1_2 (J2.21), MCU134A_180pin_Edge_Connector (EC2.146)
CON2_PIN23: MCU134A_High_Density_Conn1_2 (J2.23), MCU134A_180pin_Edge_Connector (EC2.144)
CON2_PIN25: MCU134A_High_Density_Conn1_2 (J2.25), MCU134A_180pin_Edge_Connector (EC2.142)
CON2_PIN26: MCU134A_High_Density_Conn1_2 (J2.26), MCU134A_180pin_Edge_Connector (EC2.132)
CON2_PIN27: MCU134A_High_Density_Conn1_2 (J2.27), MCU134A_180pin_Edge_Connector (EC2.140)
CON2_PIN28: MCU134A_High_Density_Conn1_2 (J2.28), MCU134A_180pin_Edge_Connector (EC2.130)
CON2_PIN29: MCU134A_High_Density_Conn1_2 (J2.29), MCU134A_180pin_Edge_Connector (EC2.138)
CON2_PIN30: MCU134A_High_Density_Conn1_2 (J2.30), MCU134A_180pin_Edge_Connector (EC1.75)
CON2_PIN31: MCU134A_High_Density_Conn1_2 (J2.31), MCU134A_180pin_Edge_Connector (EC2.155)
CON2_PIN32: MCU134A_High_Density_Conn1_2 (J2.32), MCU134A_180pin_Edge_Connector (EC1.77)
CON2_PIN33: MCU134A_High_Density_Conn1_2 (J2.33), MCU134A_180pin_Edge_Connector (EC2.153)
CON2_PIN34: MCU134A_High_Density_Conn1_2 (J2.34), MCU134A_180pin_Edge_Connector (EC1.79)
CON2_PIN35: MCU134A_High_Density_Conn1_2 (J2.35), MCU134A_180pin_Edge_Connector (EC2.151)
CON2_PIN36: MCU134A_High_Density_Conn1_2 (J2.36), MCU134A_180pin_Edge_Connector (EC1.81)
CON2_PIN38: MCU134A_High_Density_Conn1_2 (J2.38), MCU134A_180pin_Edge_Connector (EC2.128)
CON2_PIN40: MCU134A_High_Density_Conn1_2 (J2.40), MCU134A_180pin_Edge_Connector (EC2.126)
CON2_PIN45: MCU134A_High_Density_Conn1_2 (J2.45), MCU134A_180pin_Edge_Connector (EC2.149)
CON2_PIN46: MCU134A_High_Density_Conn1_2 (J2.46), MCU134A_180pin_Edge_Connector (EC2.124)
CON2_PIN47: MCU134A_High_Density_Conn1_2 (J2.47), MCU134A_180pin_Edge_Connector (EC2.147)
CON2_PIN48: MCU134A_High_Density_Conn1_2 (J2.48), MCU134A_180pin_Edge_Connector (EC2.122)
CON2_PIN49: MCU134A_High_Density_Conn1_2 (J2.49), MCU134A_180pin_Edge_Connector (EC2.145)
CON2_PIN50: MCU134A_High_Density_Conn1_2 (J2.50), MCU134A_180pin_Edge_Connector (EC2.133)
CON2_PIN51: MCU134A_High_Density_Conn1_2 (J2.51), MCU134A_180pin_Edge_Connector (EC2.143)
CON2_PIN52: MCU134A_High_Density_Conn1_2 (J2.52), MCU134A_180pin_Edge_Connector (EC2.131)
CON2_PIN53: MCU134A_High_Density_Conn1_2 (J2.53), MCU134A_180pin_Edge_Connector (EC2.141)
CON2_PIN54: MCU134A_High_Density_Conn1_2 (J2.54), MCU134A_180pin_Edge_Connector (EC2.129)
CON2_PIN55: MCU134A_High_Density_Conn1_2 (J2.55), MCU134A_180pin_Edge_Connector (EC2.139)
CON2_PIN56: MCU134A_High_Density_Conn1_2 (J2.56), MCU134A_180pin_Edge_Connector (EC2.127)
CON2_PIN57: MCU134A_High_Density_Conn1_2 (J2.57), MCU134A_180pin_Edge_Connector (EC2.137)
CON2_PIN58: MCU134A_High_Density_Conn1_2 (J2.58), MCU134A_180pin_Edge_Connector (EC2.125)
CON2_PIN59: MCU134A_High_Density_Conn1_2 (J2.59), MCU134A_180pin_Edge_Connector (EC2.134)
CON2_PIN60: MCU134A_High_Density_Conn1_2 (J2.60), MCU134A_180pin_Edge_Connector (EC2.123)
CON3_PIN2: MCU134A_High_Density_Conn3_4 (J3.2), MCU134A_180pin_Edge_Connector (EC2.152)
CON3_PIN4: MCU134A_High_Density_Conn3_4 (J3.4), MCU134A_180pin_Edge_Connector (EC2.154)
CON3_PIN6: MCU134A_High_Density_Conn3_4 (J3.6), MCU134A_180pin_Edge_Connector (EC2.156)
CON3_PIN8: MCU134A_High_Density_Conn3_4 (J3.8), MCU134A_180pin_Edge_Connector (EC2.159)
CON3_PIN10: MCU134A_High_Density_Conn3_4 (J3.10), MCU134A_180pin_Edge_Connector (EC2.161)
CON3_PIN12: MCU134A_High_Density_Conn3_4 (J3.12), MCU134A_180pin_Edge_Connector (EC2.163)
CON3_PIN14: MCU134A_High_Density_Conn3_4 (J3.14), MCU134A_180pin_Edge_Connector (EC2.165)
CON3_PIN16: MCU134A_High_Density_Conn3_4 (J3.16), MCU134A_180pin_Edge_Connector (EC2.167)
CON3_PIN18: MCU134A_High_Density_Conn3_4 (J3.18), MCU134A_180pin_Edge_Connector (EC2.169)
CON3_PIN20: MCU134A_High_Density_Conn3_4 (J3.20), MCU134A_180pin_Edge_Connector (EC2.160)
CON3_PIN22: MCU134A_High_Density_Conn3_4 (J3.22), MCU134A_180pin_Edge_Connector (EC2.162)
CON3_PIN24: MCU134A_High_Density_Conn3_4 (J3.24), MCU134A_180pin_Edge_Connector (EC2.164)
CON3_PIN26: MCU134A_High_Density_Conn3_4 (J3.26), MCU134A_180pin_Edge_Connector (EC2.166)
CON3_PIN28: MCU134A_High_Density_Conn3_4 (J3.28), MCU134A_180pin_Edge_Connector (EC2.168)
CON3_PIN29: MCU134A_High_Density_Conn3_4 (J3.29), MCU134A_180pin_Edge_Connector (EC1.113)
CON3_PIN30: MCU134A_High_Density_Conn3_4 (J3.30), MCU134A_180pin_Edge_Connector (EC2.170)
CON3_PIN31: MCU134A_High_Density_Conn3_4 (J3.31), MCU134A_180pin_Edge_Connector (EC2.173)
CON3_PIN33: MCU134A_High_Density_Conn3_4 (J3.33), MCU134A_180pin_Edge_Connector (EC2.171)
CON3_PIN35: MCU134A_High_Density_Conn3_4 (J3.35), MCU134A_180pin_Edge_Connector (EC2.177)
CON3_PIN37: MCU134A_High_Density_Conn3_4 (J3.37), MCU134A_180pin_Edge_Connector (EC2.175)
CON3_PIN39: MCU134A_High_Density_Conn3_4 (J3.39), MCU134A_180pin_Edge_Connector (EC2.172)
CON3_PIN57: MCU134A_High_Density_Conn3_4 (J3.57), MCU134A_180pin_Edge_Connector (EC2.148)
CON3_PIN59: MCU134A_High_Density_Conn3_4 (J3.59), MCU134A_180pin_Edge_Connector (EC2.150)
DAC_SPI_CLK: MCU134A_FSI_Header (J7.13), MCU134A_High_Density_Conn1_2 (J1.41), MCU134A_180pin_Edge_Connector (EC1.71)
DAC_SPI_PICO: MCU134A_FSI_Header (J7.14), MCU134A_High_Density_Conn1_2 (J1.45), MCU134A_180pin_Edge_Connector (EC1.67)
DAC_SPI_POCI: MCU134A_FSI_Header (J7.15), MCU134A_High_Density_Conn1_2 (J1.43), MCU134A_180pin_Edge_Connector (EC1.69)
DAC_SPI_PTE: MCU134A_FSI_Header (J7.16), MCU134A_High_Density_Conn1_2 (J1.76), MCU134A_180pin_Edge_Connector (EC1.93)
ECAT_PHY0_CLK: MCU134A_EtherCAT_PHY_0 (R32.1), MCU134A_High_Density_Conn3_4 (J3.117)
ECAT_PHY1_CLK: MCU134A_EtherCAT_PHY_1 (R23.1), MCU134A_High_Density_Conn3_4 (J3.119)
EEPROM_I2CSCL: MCU134A_FSI_Header (J7.12), MCU134A_High_Density_Conn1_2 (J1.23)
EEPROM_I2CSDA: MCU134A_FSI_Header (J7.11), MCU134A_High_Density_Conn1_2 (J1.25)
ESC_I2C_SCL: MCU134A_EtherCAT_PHY_0 (R91.1 U8.6), MCU134A_High_Density_Conn3_4 (J3.109)
ESC_I2C_SDA: MCU134A_EtherCAT_PHY_0 (R92.1 U8.5), MCU134A_High_Density_Conn3_4 (J3.107)
ESC_LED_ERR: MCU134A_EtherCAT_PHY_0 (R94.1 U7.1), MCU134A_High_Density_Conn3_4 (J3.105)
ESC_LED_LINK0_ACTIVE: MCU134A_EtherCAT_PHY_0 (J11.12), MCU134A_High_Density_Conn3_4 (J3.83)
ESC_LED_LINK1_ACTIVE: MCU134A_EtherCAT_PHY_1 (J5.12), MCU134A_High_Density_Conn3_4 (J3.85)
ESC_LED_RUN: MCU134A_EtherCAT_PHY_0 (R95.1 U7.3), MCU134A_High_Density_Conn3_4 (J3.103)
ESC_MDIO_CLK: MCU134A_EtherCAT_PHY_0 (U3.12), MCU134A_EtherCAT_PHY_1 (U1.12), MCU134A_High_Density_Conn3_4 (J3.97)
ESC_MDIO_DATA: MCU134A_EtherCAT_PHY_0 (R58.2 U3.11), MCU134A_EtherCAT_PHY_1 (R3.1 U1.11), MCU134A_High_Density_Conn3_4 (J3.99)
ESC_PHY0_LINKSTATUS: MCU134A_EtherCAT_PHY_0 (J11.1 R88.2 U3.31), MCU134A_High_Density_Conn3_4 (J3.87)
ESC_PHY1_LINKSTATUS: MCU134A_EtherCAT_PHY_1 (J5.1 R33.2 U1.31), MCU134A_High_Density_Conn3_4 (J3.89)
ESC_PHY_RESETn: MCU134A_EtherCAT_PHY_0 (R56.1 U3.32), MCU134A_EtherCAT_PHY_1 (R1.1 U1.32), MCU134A_High_Density_Conn3_4 (J3.101)
ESC_RX0_CLK: MCU134A_EtherCAT_PHY_0 (R64.1), MCU134A_High_Density_Conn3_4 (J3.100)
ESC_RX0_DATA0: MCU134A_EtherCAT_PHY_0 (R78.1 R86.2), MCU134A_High_Density_Conn3_4 (J3.102)
ESC_RX0_DATA1: MCU134A_EtherCAT_PHY_0 (R70.1 R84.2), MCU134A_High_Density_Conn3_4 (J3.104)
ESC_RX0_DATA2: MCU134A_EtherCAT_PHY_0 (R63.1 R71.1), MCU134A_High_Density_Conn3_4 (J3.106)
ESC_RX0_DATA3: MCU134A_EtherCAT_PHY_0 (R62.1 R72.1), MCU134A_High_Density_Conn3_4 (J3.108)
ESC_RX0_DV: MCU134A_EtherCAT_PHY_0 (R68.1 R85.2), MCU134A_High_Density_Conn3_4 (J3.113)
ESC_RX0_ERR: MCU134A_EtherCAT_PHY_0 (R61.1 R73.1), MCU134A_High_Density_Conn3_4 (J3.111)
ESC_RX1_CLK: MCU134A_EtherCAT_PHY_1 (R9.1), MCU134A_High_Density_Conn3_4 (J3.76)
ESC_RX1_DATA0: MCU134A_EtherCAT_PHY_1 (R24.1 R31.2), MCU134A_High_Density_Conn3_4 (J3.78)
ESC_RX1_DATA1: MCU134A_EtherCAT_PHY_1 (R15.1 R29.2), MCU134A_High_Density_Conn3_4 (J3.80)
ESC_RX1_DATA2: MCU134A_EtherCAT_PHY_1 (R8.1 R16.1), MCU134A_High_Density_Conn3_4 (J3.82)
ESC_RX1_DATA3: MCU134A_EtherCAT_PHY_1 (R7.1 R17.1), MCU134A_High_Density_Conn3_4 (J3.84)
ESC_RX1_DV: MCU134A_EtherCAT_PHY_1 (R13.1 R30.2), MCU134A_High_Density_Conn3_4 (J3.93)
ESC_RX1_ERR: MCU134A_EtherCAT_PHY_1 (R6.1 R18.1), MCU134A_High_Density_Conn3_4 (J3.95)
ESC_TX0_CLK: MCU134A_EtherCAT_PHY_0 (R74.1 R83.2), MCU134A_High_Density_Conn3_4 (J3.112)
ESC_TX0_DATA0: MCU134A_EtherCAT_PHY_0 (R69.2), MCU134A_High_Density_Conn3_4 (J3.114)
ESC_TX0_DATA1: MCU134A_EtherCAT_PHY_0 (R67.2), MCU134A_High_Density_Conn3_4 (J3.116)
ESC_TX0_DATA2: MCU134A_EtherCAT_PHY_0 (R66.2), MCU134A_High_Density_Conn3_4 (J3.118)
ESC_TX0_DATA3: MCU134A_EtherCAT_PHY_0 (R65.2), MCU134A_High_Density_Conn3_4 (J3.120)
ESC_TX0_ENA: MCU134A_EtherCAT_PHY_0 (R60.2), MCU134A_High_Density_Conn3_4 (J3.115)
ESC_TX1_CLK: MCU134A_EtherCAT_PHY_1 (R20.1 R28.2), MCU134A_High_Density_Conn3_4 (J3.88)
ESC_TX1_DATA0: MCU134A_EtherCAT_PHY_1 (R14.2), MCU134A_High_Density_Conn3_4 (J3.90)
ESC_TX1_DATA1: MCU134A_EtherCAT_PHY_1 (R12.2), MCU134A_High_Density_Conn3_4 (J3.92)
ESC_TX1_DATA2: MCU134A_EtherCAT_PHY_1 (R11.2), MCU134A_High_Density_Conn3_4 (J3.94)
ESC_TX1_DATA3: MCU134A_EtherCAT_PHY_1 (R10.2), MCU134A_High_Density_Conn3_4 (J3.96)
ESC_TX1_ENA: MCU134A_EtherCAT_PHY_1 (R5.2), MCU134A_High_Density_Conn3_4 (J3.91)
FSIRX_CLK: MCU134A_FSI_Header (J8.3), MCU134A_High_Density_Conn1_2 (J1.55)
FSIRX_D0: MCU134A_FSI_Header (J8.1), MCU134A_High_Density_Conn1_2 (J1.59)
FSIRX_D1: MCU134A_FSI_Header (J8.2), MCU134A_High_Density_Conn1_2 (J1.57)
FSITX_CLK: MCU134A_FSI_Header (J8.7), MCU134A_High_Density_Conn1_2 (J1.49)
FSITX_D0: MCU134A_FSI_Header (J8.5), MCU134A_High_Density_Conn1_2 (J1.53)
FSITX_D1: MCU134A_FSI_Header (J8.6), MCU134A_High_Density_Conn1_2 (J1.51)
HSEC_PIN9: MCU134A_180pin_Edge_Connector (EC1.9), MCU134A_ADC (R97.1 U4.1)
HSEC_PIN11: MCU134A_180pin_Edge_Connector (EC1.11), MCU134A_ADC (R98.1 U4.2)
HSEC_PIN12: MCU134A_180pin_Edge_Connector (EC1.12), MCU134A_ADC (R109.1 U10.1)
HSEC_PIN14: MCU134A_180pin_Edge_Connector (EC1.14), MCU134A_ADC (R110.1 U10.2)
HSEC_PIN15: MCU134A_180pin_Edge_Connector (EC1.15), MCU134A_ADC (R99.1 U4.5)
HSEC_PIN17: MCU134A_180pin_Edge_Connector (EC1.17), MCU134A_ADC (R100.1 U4.4)
HSEC_PIN18: MCU134A_180pin_Edge_Connector (EC1.18), MCU134A_ADC (R111.1 U10.5)
HSEC_PIN20: MCU134A_180pin_Edge_Connector (EC1.20), MCU134A_ADC (R112.1 U10.4)
HSEC_PIN21: MCU134A_180pin_Edge_Connector (EC1.21), MCU134A_ADC (R101.1 U5.1)
HSEC_PIN23: MCU134A_180pin_Edge_Connector (EC1.23), MCU134A_ADC (R102.1 U5.2)
HSEC_PIN24: MCU134A_180pin_Edge_Connector (EC1.24), MCU134A_ADC (R113.1 U11.1)
HSEC_PIN25: MCU134A_180pin_Edge_Connector (EC1.25), MCU134A_ADC (R103.1 U5.5)
HSEC_PIN26: MCU134A_180pin_Edge_Connector (EC1.26), MCU134A_ADC (R114.1 U11.2)
HSEC_PIN27: MCU134A_180pin_Edge_Connector (EC1.27), MCU134A_ADC (R104.1 U5.4)
HSEC_PIN28: MCU134A_180pin_Edge_Connector (EC1.28), MCU134A_ADC (R115.1 U11.5)
HSEC_PIN30: MCU134A_180pin_Edge_Connector (EC1.30), MCU134A_ADC (R116.1 U11.4)
HSEC_PIN31: MCU134A_180pin_Edge_Connector (EC1.31), MCU134A_ADC (C25.1 R105.1 U9.1)
HSEC_PIN33: MCU134A_180pin_Edge_Connector (EC1.33), MCU134A_ADC (C25.2 R106.1 U9.2)
HSEC_PIN34: MCU134A_180pin_Edge_Connector (EC1.34), MCU134A_ADC (R117.1 U12.1)
HSEC_PIN36: MCU134A_180pin_Edge_Connector (EC1.36), MCU134A_ADC (R118.1 U12.2)
HSEC_PIN37: MCU134A_180pin_Edge_Connector (EC1.37), MCU134A_ADC (R107.1 U9.5)
HSEC_PIN39: MCU134A_180pin_Edge_Connector (EC1.39), MCU134A_ADC (R108.1 U9.4)
HSEC_PIN40: MCU134A_180pin_Edge_Connector (EC1.40), MCU134A_ADC (R119.1 U12.5)
HSEC_PIN42: MCU134A_180pin_Edge_Connector (EC1.42), MCU134A_ADC (R120.1 U12.4)
MCU_SCI_RX: MCU134A_FSI_Header (J7.9), MCU134A_High_Density_Conn1_2 (J1.33), MCU134A_180pin_Edge_Connector (EC1.76)
MCU_SCI_TX: MCU134A_FSI_Header (J7.10), MCU134A_High_Density_Conn1_2 (J1.31), MCU134A_180pin_Edge_Connector (EC1.78)
MCU_TCK: MCU134A_FSI_Header (J7.4), MCU134A_High_Density_Conn1_2 (J1.22), MCU134A_180pin_Edge_Connector (EC1.5)
MCU_TDI: MCU134A_FSI_Header (J7.5), MCU134A_High_Density_Conn1_2 (J1.19), MCU134A_180pin_Edge_Connector (EC1.8)
MCU_TDO: MCU134A_FSI_Header (J7.6), MCU134A_High_Density_Conn1_2 (J1.21), MCU134A_180pin_Edge_Connector (EC1.6)
MCU_TMS: MCU134A_FSI_Header (J7.3), MCU134A_High_Density_Conn1_2 (J1.24), MCU134A_180pin_Edge_Connector (EC1.3)

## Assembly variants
001: not fitted C4 C5 C6 C7 C25 C43 C44 C45 C46 C62 C63 C64 C65 C66 C67 C68 C69 C70 C71 C72 C73 C74 C75 C76 C77 C78 C79 C80 C81 C82 C83 C84 C85 J4 R3 R36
